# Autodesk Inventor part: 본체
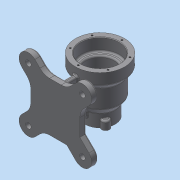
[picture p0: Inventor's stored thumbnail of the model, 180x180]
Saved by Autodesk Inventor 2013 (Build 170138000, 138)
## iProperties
Created: 2017-03
Part Number: 본체
Material: 일반
Document SubType Name: Modeling
Designer: dgall
Density: 1 g/cm^3
Author: dgall
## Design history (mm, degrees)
sketch "스케치2"
  geometry: L1 (45, 50)-(45, 30); L2 (45, 30)-(36, 19); L3 (36, 19)-(36, -15); L4 (36, -15)-(27.5, -27); L5 (27.5, -27)-(27.5, -50); L6 (27.5, -50)-(0, -50); L7 (0, -50)-(0, 50); L8 (0, 50)-(45, 50); 2 further points
  constraints: 16 end point, 2 coincident, 2 parallel, 2 perpendicular, 1 midpoint, 1 vertical
  dimensions: "d6" = 20 distance of L1.start L1.end; "d8" = 31 vertical distance of L1.start L2.end; "d9" = 65 vertical distance of L1.start L3.end; "d10" = 23 distance of L4.end L5.end; "d11" = 100 vertical distance of L1.start L5.end; "d12" = 90 diameter of L1 L7; "d13" = 72 diameter of L3 L7; "d14" = 55 diameter of L5 L7
revolve "회전1" sketch "스케치2" stored, may be unused: angle "d15" = 90 deg
sketch "스케치3"
  geometry: C1 r 5 at (0, 0); 1 further point
  constraints: 1 centre point, 1 coincident
  dimensions: "d16" = 10 diameter of C1
extrude "돌출1" join sketch "스케치3" distance "d17" = 40; taper "d18" = 0 deg
node "작업 평면1"
sketch "스케치4"
  geometry: L1 (-45, 45)-(45, 45); L2 (45, 45)-(45, -45); L3 (45, -45)-(-45, -45); L4 (-45, -45)-(-45, 45); L5 (-37.477, 61.518)-(-20.958, 45); L6 (-61.518, 37.477)-(-45, 20.958); L7 (37.477, 61.518)-(20.958, 45); L8 (61.518, 37.477)-(45, 20.958); L9 (37.477, -61.518)-(20.958, -45); L10 (45, -20.958)-(61.518, -37.477); L11 (-61.518, -37.477)-(-45, -20.958); L12 (-20.958, -45)-(-37.477, -61.518); A1 r 70 centre (0, 0) between (-49.497, 49.497) and (-59.97, -36.106); A2 r 17 centre (-49.497, 49.497) between (-37.477, 61.518) and (-61.518, 37.477); A3 r 17 centre (-49.497, -49.497) between (-61.518, -37.477) and (-37.477, -61.518); A4 r 17 centre (49.497, -49.497) between (37.477, -61.518) and (61.518, -37.477); A5 r 17 centre (49.497, 49.497) between (61.518, 37.477) and (37.477, 61.518); 3 further points
  constraints: 24 end point, 13 point on circle, 8 point on line, 7 tangent, 5 centre point, 4 equal length, 3 parallel, 3 perpendicular, 2 midpoint, 1 coincident, 1 horizontal, 1 horizontal alignment, 1 vertical alignment, 17 other
  dimensions: "d20" = 90 distance of L1.start L1.end; "d22" = 140 diameter of A1; "d25" = 45 deg dimension on point (0, 0) point (-45, 0) A1.start; "d28" = 360 deg dimension on point (0, 0) A1.start (derived); "d114" = 34 diameter of A2
extrude "돌출2" join sketch "스케치4" distance "d30" = 12; taper "d31" = 0 deg
fillet "모깎기1" dims "d32" = 25
sketch "스케치5"
  geometry: L1 (-4, -37)-(4, -37); L2 (4, -37)-(4, 37); L3 (4, 37)-(-4, 37); L4 (-4, 37)-(-4, -37); 3 further points
  constraints: 8 end point, 2 midpoint, 2 parallel, 1 horizontal, 1 horizontal alignment, 1 perpendicular, 1 vertical alignment
  dimensions: "d36" = 74 distance of L3.end L1.start; "d38" = 8 distance of L2.end L3.end
extrude "돌출3" join sketch "스케치5" stored distance "d39" = 0; taper "d40" = 0 deg
sketch "스케치6"
  geometry: L1 (-28.281, -70)-(-37.477, -70) reference; L2 (-10.603, -70)-(-28.281, -70) reference; L3 (-25, -70)-(-18.14, -31.096); L4 (18.14, -31.096)-(25, -70); L5 (37.477, -70)-(20.958, -70) reference; L6 (20.958, -70)-(-10.603, -70) reference; A1 r 36 centre (0, 0) between (4, -35.777) and (-4, -35.777) reference; 1 further point
  constraints: 4 end point, 2 point on circle, 2 point on line, 1 horizontal alignment
  dimensions: "d41" = 25 horizontal distance of L3.start point (0, 0); "d42" = 25 horizontal distance of L4.end point (0, 0); "d43" = 100 deg angle of L1 L3
extrude "돌출4" join sketch "스케치6" stored distance "d44" = 8; taper "d45" = 0 deg
sketch "스케치7"
  geometry: C1 r 45 at (0, 0) reference; C2 r 35 at (0, 0)
  constraints: 1 centre point, 1 coincident
  dimensions: "d46" = 70 diameter of C2
extrude "돌출5" cut sketch "스케치7" distance "d47" = 23; taper "d48" = 0 deg
sketch "스케치8"
  geometry: C1 r 35 at (0, 0) reference; C2 r 26 at (0, 0)
  constraints: 1 centre point, 1 coincident
  dimensions: "d49" = 52 diameter of C2
extrude "돌출6" cut sketch "스케치8" distance "d50" = 47; taper "d51" = 0 deg
sketch "스케치9"
  geometry: C1 r 26 at (0, 0) reference; C2 r 17.5 at (0, 0)
  constraints: 1 centre point, 1 coincident
  dimensions: "d52" = 35 diameter of C2
extrude "돌출7" cut sketch "스케치9" distance "d54" = 30; taper "d55" = 0 deg
hole "구멍1" diameter "d58" = 4.134; stored, may be unused: countersink angle "d62" = 90 deg, drill point angle "d64" = 118 deg; dims "d59" = 100, "d60" = 4, "d61" = 2, "d63" = 8, "d65" = 10, "d66" = 10
sketch "스케치10"
  geometry: C1 r 17.5 at (0, 0) reference; C2 r 7 at (0, 27.5); C3 r 7 at (-23.816, -13.75); C4 r 7 at (23.816, -13.75); 1 further point
  constraints: 3 centre point, 2 vertical alignment, 8 other
  dimensions: "d67" = 14 diameter of C2; "d71" = 360 deg dimension on C1.centre C2.centre (derived)
extrude "돌출8" join sketch "스케치10" distance "d73" = 15; taper "d74" = 0 deg
sketch "스케치11"
  geometry: A1 r 7 centre (0, 0) between (6.943, -0.891) and (-6.943, -0.891) reference; A2 r 7 centre (-23.816, -41.25) between (-26.516, -34.792) and (-19.573, -46.817) reference; A3 r 7 centre (23.816, -41.25) between (19.573, -46.817) and (26.516, -34.792) reference; 3 further points
  constraints: 3 coincident
hole "구멍2" sketch "스케치11" at (-23.816, -41.25), (23.816, -41.25), (0, 0) diameter "d75" = 3.242; stored, may be unused: countersink angle "d79" = 90 deg, drill point angle "d81" = 118 deg; dims "d76" = 9, "d77" = 4, "d78" = 2, "d80" = 11
sketch "스케치12"
  geometry: C1 r 35 at (0, 0) reference; 1 further point
  constraints: 1 vertical alignment
  dimensions: "d82" = 40 distance of C1.centre point (0, 40)
hole "구멍3" sketch "스케치12" at (0, 40) diameter "d83" = 3.242; stored, may be unused: countersink angle "d87" = 90 deg, drill point angle "d89" = 118 deg; dims "d84" = 9, "d85" = 4, "d86" = 2, "d88" = 11
sketch "스케치13"
  geometry: L1 (20.958, 45)-(-10.603, 45) reference; 3 further points
  constraints: 1 other
  dimensions: "d93" = 35 distance of point (35, 0) point (0, 0); "d94" = 45 distance from line of point (35, 0) L1
feature "엠보싱1" sketch "스케치13" dims "d6" = 20, "d8" = 31, "d9" = 65, "d10" = 23, "d11" = 100, "d12" = 90, "d13" = 72, "d14" = 55, "d20" = 90, "d22" = 140, "d25" = 45 deg, "d28" = 360 deg (derived), "d95" = 0.5, "d96" = 0, "d114" = 34
fillet "모깎기2" dims "d97" = 3
sketch "스케치14"
  geometry: A1 r 14 centre (-49.497, 49.497) between (-39.598, 59.397) and (-59.397, 39.598) reference; A2 r 14 centre (-49.497, -49.497) between (-59.397, -39.598) and (-39.598, -59.397) reference; A3 r 14 centre (49.497, -49.497) between (39.598, -59.397) and (59.397, -39.598) reference; A4 r 14 centre (49.497, 49.497) between (59.397, 39.598) and (39.598, 59.397) reference; 8 further points
  constraints: 4 coincident
hole "구멍4" sketch "스케치14" at (-49.497, -49.497), (-49.497, 49.497), (49.497, 49.497), (49.497, -49.497) diameter "d98" = 10; stored, may be unused: countersink angle "d102" = 90 deg, drill point angle "d104" = 118 deg; dims "d99" = 9, "d100" = 4, "d101" = 2, "d103" = 11
fillet "모깎기3" dims "d105" = 3
fillet "모깎기4" dims "d106" = 3
fillet "모깎기5" dims "d107" = 3
fillet "모깎기6" dims "d108" = 1
chamfer "모따기1" distance "d109" = 1; stored, may be unused: second distance "d110" = 2, angle "d111" = 45 deg
fillet "모깎기7" dims "d112" = 3
node "솔리드1"
pattern_circular "원형 패턴1" dims angle "d91" = 360 deg
other parameters: "d19" = -82
